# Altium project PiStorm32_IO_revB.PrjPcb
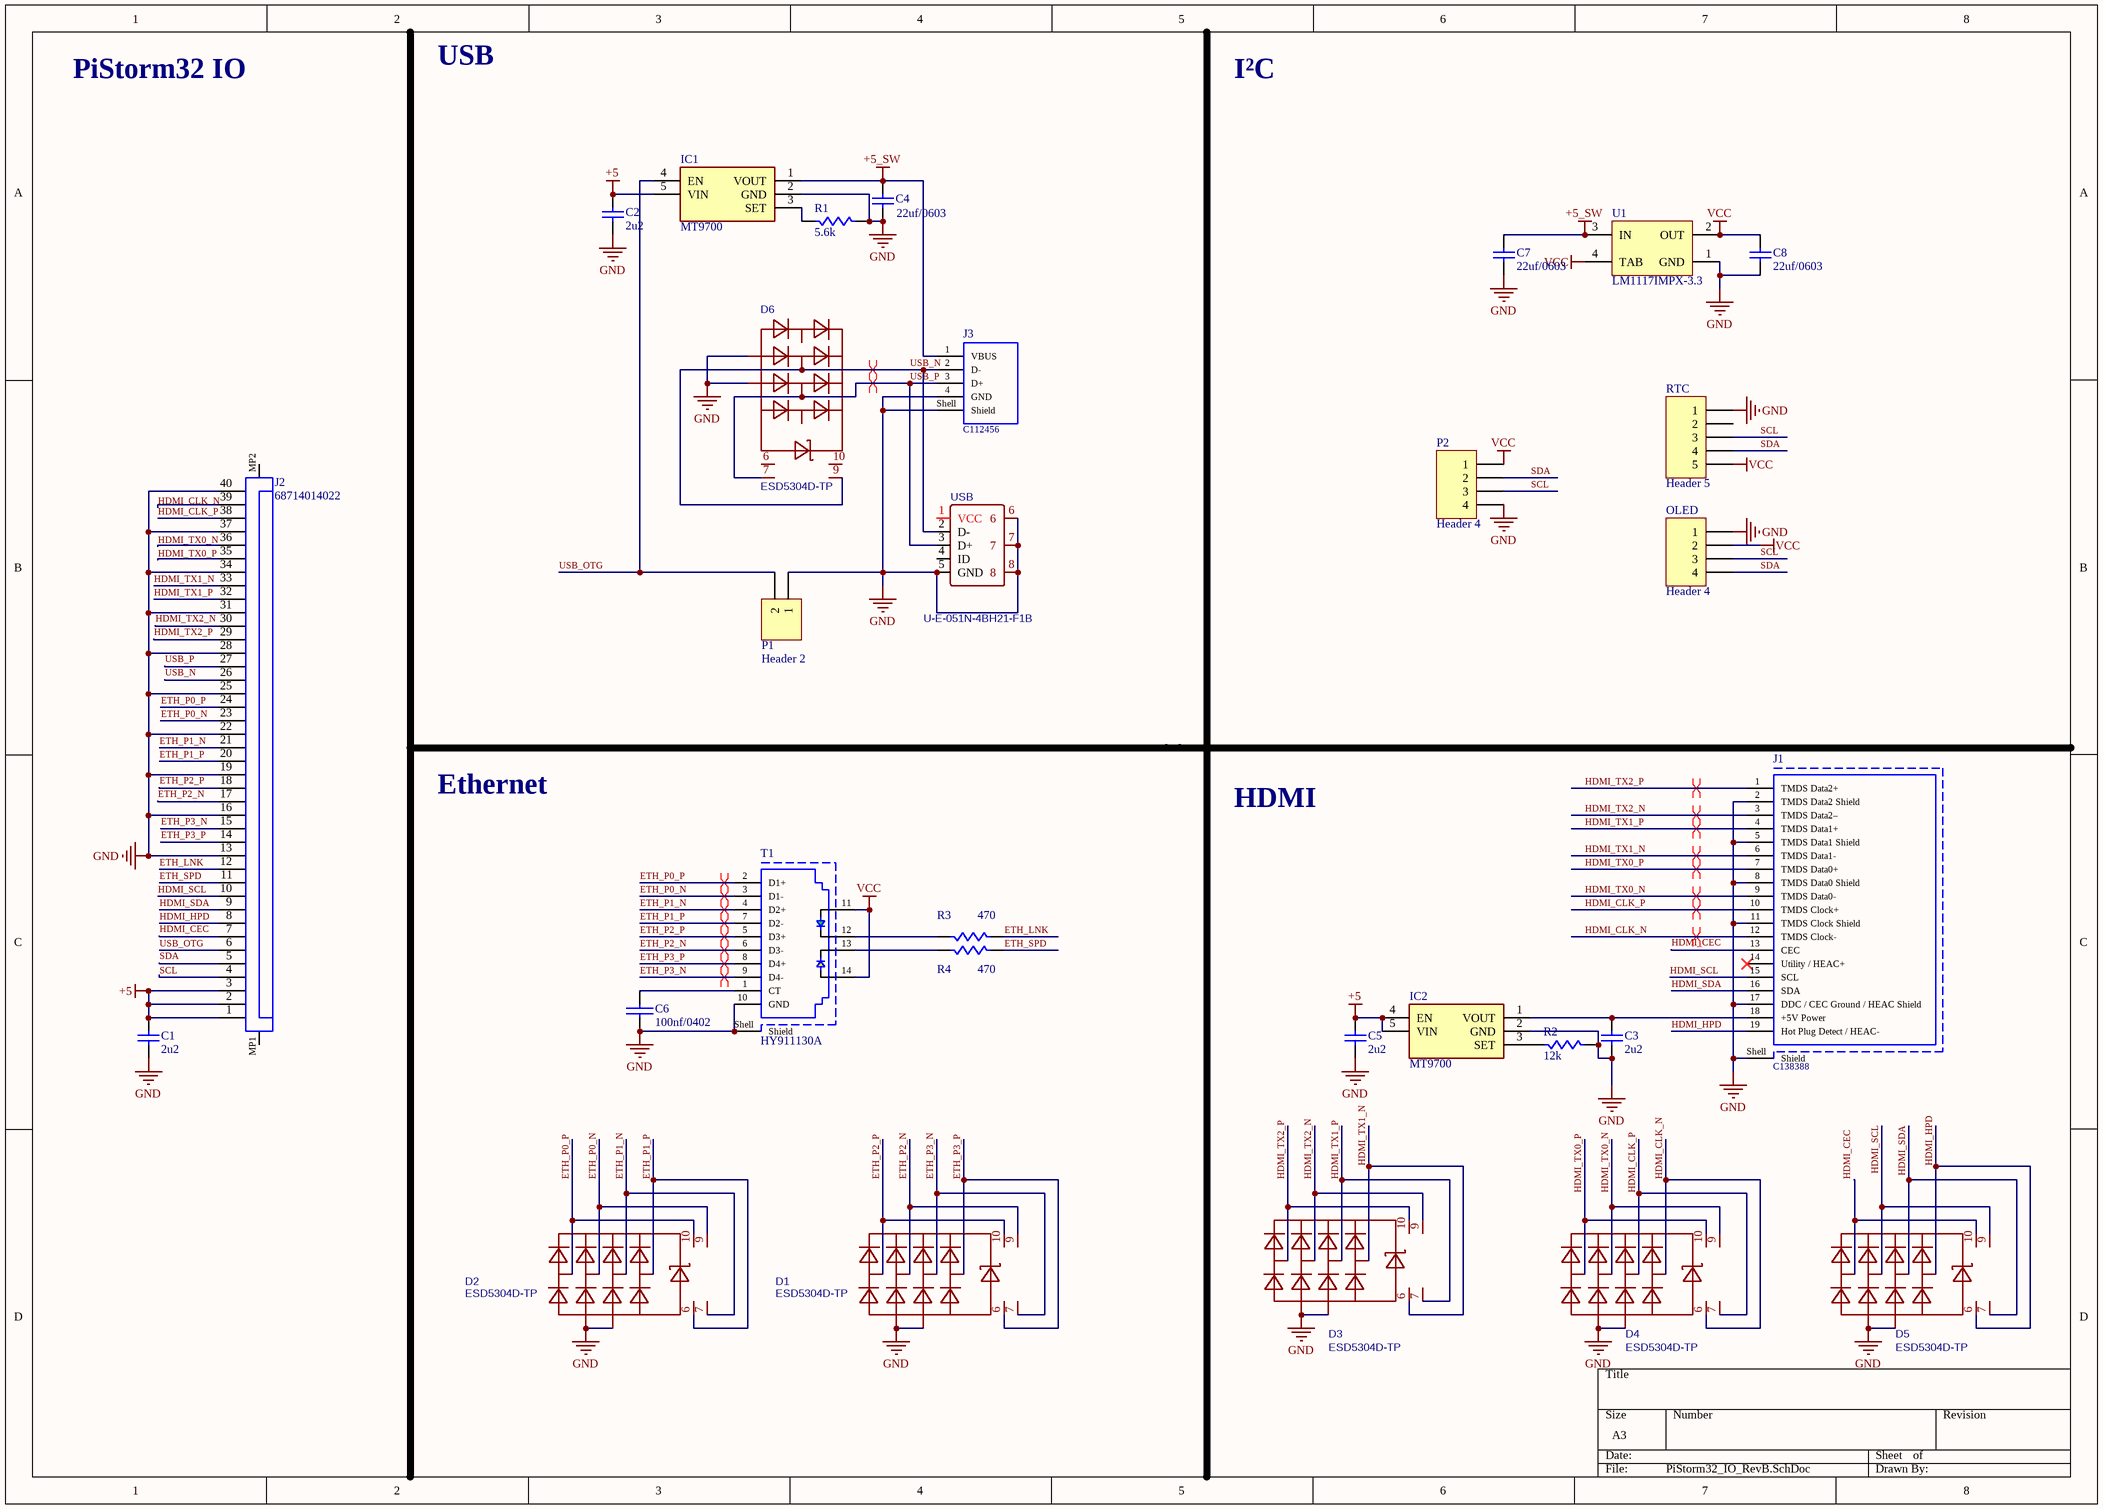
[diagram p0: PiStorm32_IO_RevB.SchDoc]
1 sheet, 30 parts. Net scope: global (net labels, ports and power ports of the same name join across sheets).
Board file: PiStorm32_IO_RevB.pcbdoc

## Sheet PiStorm32_IO_RevB.SchDoc
size A3

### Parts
C1  value 2u2  [1608[0603]]  (hidden comment: Cap Semi)
C2  value 2u2  [1608[0603]]  (hidden comment: Cap Semi)
C3  value 2u2  [1608[0603]]  (hidden comment: Cap Semi)
C4  value 22uf/0603  [RCL_C0603K]  (hidden comment: Cap Semi)
C5  value 2u2  [1608[0603]]  (hidden comment: Cap Semi)
C6  100nf/0402  [005-00008]
C7  value 22uf/0603  [RCL_C0603K]  (hidden comment: Cap Semi)
C8  value 22uf/0603  [RCL_C0603K]  (hidden comment: Cap Semi)
D1  ESD5304D-TP  [DFN2510-10_L2.5-W1.0-P0.50-BL]
D2  ESD5304D-TP  [DFN2510-10_L2.5-W1.0-P0.50-BL]
D3  ESD5304D-TP  [DFN2510-10_L2.5-W1.0-P0.50-BL]
D4  ESD5304D-TP  [DFN2510-10_L2.5-W1.0-P0.50-BL]
D5  ESD5304D-TP  [DFN2510-10_L2.5-W1.0-P0.50-BL]
D6  ESD5304D-TP  [DFN2510-10_L2.5-W1.0-P0.50-BL]
IC1  MT9700  [SOT95P280X135-5N]
IC2  MT9700  [SOT95P280X135-5N]
J1  C138388  [685119134923]
J2  68714014022  [68714014022]
J3  C112456  [61400416021]
OLED  Header 4  [HDR1X4]  (no BOM)
P1  Header 2  [HDR1X2]  (no BOM)
P2  Header 4  [HDR1X4]  (no BOM)
R1  5.6k  [005-00008]
R2  12k  [005-00008]
R3  470  [005-00008]
R4  470  [005-00008]
RTC  Header 5  [HDR1X5]  (no BOM)
T1  HY911130A  [HY911130A]
U1  LM1117IMPX-3.3  [MP04A_N]
USB  U-E-051N-4BH21-F1B  [MICRO-USB-SMD_U-E-051N-4BH21-F1B]

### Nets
+5: C1.1 C2.1 C5.1 IC1.5(VIN) IC2.4(EN) IC2.5(VIN) J2.1 J2.2 J2.3
+5_SW: C4.1 C7.1 IC1.1(VOUT) J3.1(VBUS) U1.3(IN)
GND: C1.2 C2.2 C3.2 C4.2 C5.2 C6.1 C7.2 C8.2 D1.3(GND) D1.8(GND) D2.3(GND) D2.8(GND) D3.3(GND) D3.8(GND) D4.3(GND) D4.8(GND) D5.3(GND) D5.8(GND) D6.3(GND) D6.8(GND) IC1.2(GND) IC2.2(GND) J1.2(TMDS_Data2_Shield) J1.5(TMDS_Data1_Shield) J1.8(TMDS_Data0_Shield) J1.11(TMDS_Clock_Shield) J1.17(DDC_/_CEC_Ground_/_HEAC_Shield) J1.Shell(Shield) J2.13 J2.16 J2.19 J2.22 J2.25 J2.28 J2.31 J2.34 J2.37 J2.40 J3.4(GND) J3.Shell(Shield) OLED.1 P1.1 P2.4 R1.1 R2.1 RTC.1 T1.10(GND) T1.Shell(Shield) U1.1(GND) USB.5(GND) USB.6 USB.7 USB.8
VCC: C8.1 OLED.2 P2.1 RTC.5 T1.11 T1.14 U1.2(OUT) U1.4(TAB)
ETH_LNK: J2.12 R3.1
ETH_P0_N: D2.2(K) D2.9(NC) J2.23 T1.3(D1-)
ETH_P0_P: D2.1(K) D2.10(NC) J2.24 T1.2(D1+)
ETH_P1_N: D2.4(K) D2.7(NC) J2.21 T1.4(D2+)
ETH_P1_P: D2.5(K) D2.6(NC) J2.20 T1.7(D2-)
ETH_P2_N: D1.2(K) D1.9(NC) J2.17 T1.6(D3-)
ETH_P2_P: D1.1(K) D1.10(NC) J2.18 T1.5(D3+)
ETH_P3_N: D1.4(K) D1.7(NC) J2.15 T1.9(D4-)
ETH_P3_P: D1.5(K) D1.6(NC) J2.14 T1.8(D4+)
ETH_SPD: J2.11 R4.1
HDMI_CEC: D5.1(K) D5.10(NC) J1.13(CEC) J2.7
HDMI_CLK_N: D4.5(K) D4.6(NC) J1.12(TMDS_Clock-) J2.39
HDMI_CLK_P: D4.4(K) D4.7(NC) J1.10(TMDS_Clock+) J2.38
HDMI_HPD: D5.5(K) D5.6(NC) J1.19(Hot_Plug_Detect_/_HEAC-) J2.8
HDMI_SCL: D5.2(K) D5.9(NC) J1.15(SCL) J2.10
HDMI_SDA: D5.4(K) D5.7(NC) J1.16(SDA) J2.9
HDMI_TX0_N: D4.2(K) D4.9(NC) J1.9(TMDS_Data0-) J2.36
HDMI_TX0_P: D4.1(K) D4.10(NC) J1.7(TMDS_Data0+) J2.35
HDMI_TX1_N: D3.5(K) D3.6(NC) J1.6(TMDS_Data1-) J2.33
HDMI_TX1_P: D3.4(K) D3.7(NC) J1.4(TMDS_Data1+) J2.32
HDMI_TX2_N: D3.2(K) D3.9(NC) J1.3(TMDS_Data2–) J2.30
HDMI_TX2_P: D3.1(K) D3.10(NC) J1.1(TMDS_Data2+) J2.29
SCL: J2.4 OLED.3 P2.3 RTC.3
SDA: J2.5 OLED.4 P2.2 RTC.4
USB_N: D6.2(K) D6.9(NC) J2.26 J3.2(D-) USB.2(D-)
USB_OTG: IC1.4(EN) J2.6 P1.2
USB_P: D6.4(K) D6.7(NC) J2.27 J3.3(D+) USB.3(D+)
NetC3_1: C3.1 IC2.1(VOUT) J1.18(+5V_Power)
NetC6_2: C6.2 T1.1(CT)
NetIC1_3: IC1.3(SET) R1.2
NetIC2_3: IC2.3(SET) R2.2
NetR3_2: R3.2 T1.12
NetR4_2: R4.2 T1.13

Not connected (* = marked no-connect by the designer): D6 1(K) 5(K) 6(NC) 10(NC); J1 14(Utility_/_HEAC+)*; J2 MP1 MP2; RTC 2; USB 1(VCC) 4(ID)

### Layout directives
differential pair: ETH_P0_N, ETH_P0_P, ETH_P1_N, ETH_P1_P, ETH_P2_N, ETH_P2_P, ETH_P3_N, ETH_P3_P, HDMI_CLK_N, HDMI_CLK_P, HDMI_TX0_N, HDMI_TX0_P, HDMI_TX1_N, HDMI_TX1_P, HDMI_TX2_N, HDMI_TX2_P, USB_N, USB_P

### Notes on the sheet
- PiStorm32 IO
- USB
- I²C
- Ethernet
- HDMI

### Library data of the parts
C1-C5 C7 C8 = Cap Semi: Capacitor (Semiconductor SIM Model)
C6 = 004-00003: Capacitor 1uF 10V Ceramic 10% 0402; Part Number: 011-00010; Manufacturer1 Part Number: 0402ZD105KAT2A; Manufacturer1: AVX; 3rd Party: {Reference Design}; Types: Ratings
D1-D6 = ESD5304D-TP: BOM_Manufacturer: TECH PUBLIC(台舟); Contributor: LCSC
IC1 IC2 = MT9700: Integrated Circuit; Manufacturer_Name: Aerosemi
J1 = 685119134923: HDMI Type A Receptacle WR-HDMI, Horizontal, SMT; Rated Current: 0.5 A; Contact Resistance: 30 mOhm; Working Voltage: 40 VDC
J2 = 68714014022: WR-FPC SMT ZIF Horizontal Top Contact, pitch 0.5mm, 40p; Manufacturer: Wurth Elektronik; Contact Resistance: 20mOhm; Pin Number: 40; Working Voltage: 50VAC; Rated Current: 0.5A
J3 = 61400416021: USB 2.0 Type A, Receptacle, Horizontal, THT; Manufacturer: Wurth Elektronik; Rated Current: 1.5A; Pin Number: 4; Interface Type: Type A; Working Voltage: 30VAC
OLED P2 = Header 4: Header, 4-Pin
P1 = Header 2: Header, 2-Pin
R1-R4 = 004-00008: RES 22 OHM 1/16W 5% 0402; Part Number: 009-00020; Manufacturer1 Part Number: RMCF0402JT22R0; Manufacturer1: Stackpole Electronics; Tolerance: 0.05; Value: 22
RTC = Header 5: Header, 5-Pin
T1 = HY911130A: LAN Transformer, THT, 10/100/1000 Base-T, Port 1x1, Tab Down; Manufacturer Part Number: 7499111446; Manufacturer: Wurth Elektronik; PoE: non-PoE; LED: green/yellow-green/yellow; USB: No; Shield Tabs: Yes
U1 = LM1117IMPX-3.3: 800mA Low-Dropout Linear Regulator, 4-pin SOT-223; Manufacturer: National Semiconductor; PackageTopMarking: XYTT*N05B; PowerWise: N; CompType: LDO IC
USB = U-E-051N-4BH21-F1B: BOM_Manufacturer: XKB Enterprise; Contributor: LCSC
